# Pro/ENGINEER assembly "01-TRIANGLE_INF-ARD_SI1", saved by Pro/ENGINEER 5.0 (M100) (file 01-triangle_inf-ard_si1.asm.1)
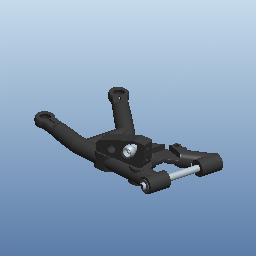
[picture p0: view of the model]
Units: millimeter Newton Second (mmNs); MM, TONNE, HOURS

Other components: 80127701-TRI_INF_AR_RENFOR_SI1, CHAPE_STD_COURTE_07B, CHAPE_STD_COURTE_07A, 80804800-SUP_TIR_BASCULE_SI1, AXE_FUSEE_SI1, 80025000-ROTULE_STD_SI1

Other named items: 80127701-TRI_INF_AR_RENFOR_01, 80022000-CHAPE_STD_COURTE_01, 80022001-CHAPE_STD_DR_01, 80804800-SUP_TIR_BASCULE_AR_01, AXE_FUSEE_01, A-DROITE, A-DESSUS, A-FACE, AA_TRI-INF, A-R0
